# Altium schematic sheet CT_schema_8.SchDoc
size 274 x 160 mm
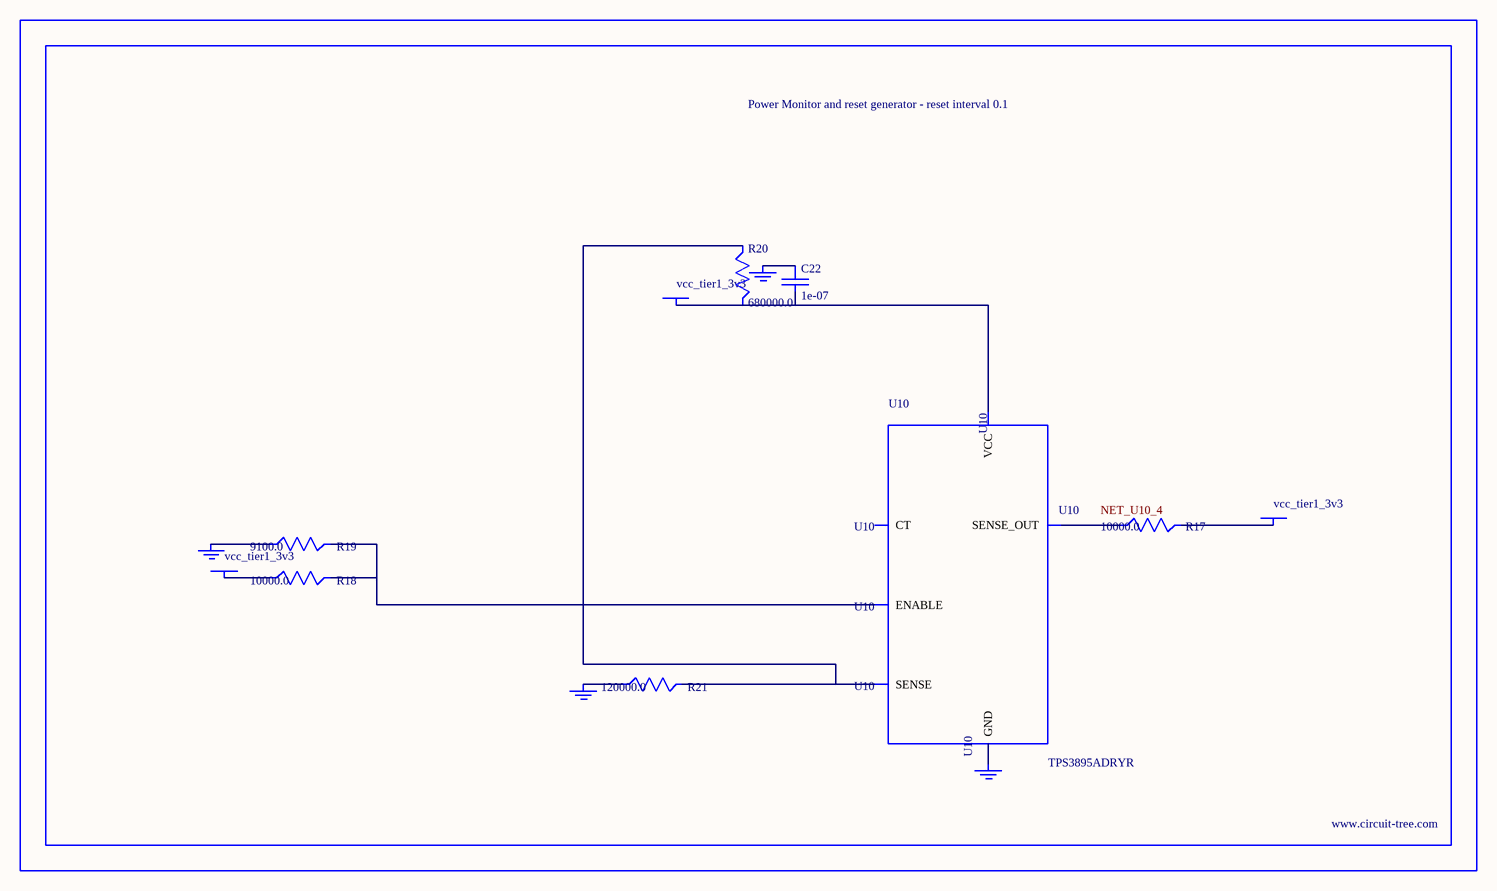
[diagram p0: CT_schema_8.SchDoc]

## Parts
BORDER7  (no value)
C22  1e-07  [C0402]
GND_INSTANCE_7_0  (no value)
GND_INSTANCE_7_1  (no value)
GND_INSTANCE_7_2  (no value)
GND_INSTANCE_7_3  (no value)
POWER_INSTANCE_7_0  vcc_tier1_3v3
POWER_INSTANCE_7_1  vcc_tier1_3v3
POWER_INSTANCE_7_2  vcc_tier1_3v3
R17  10000.0  [R0603]
R18  10000.0  [R0603]
R19  9100.0  [R0603]
R20  680000.0  [R0603]
R21  120000.0  [R0603]
U10  TPS3895ADRYR  [SON-6]

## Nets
NetC22_1: C22.1 GND_INSTANCE_7_2.0(GND)
NetC22_2: C22.2 POWER_INSTANCE_7_2.0(PWR) R20.2 U10.6(VCC)
NetGND_INSTANCE_7_0_0: GND_INSTANCE_7_0.0(GND) R19.1
NetGND_INSTANCE_7_1_0: GND_INSTANCE_7_1.0(GND) R21.1
NetGND_INSTANCE_7_3_0: GND_INSTANCE_7_3.0(GND) U10.2(GND)
NetPOWER_INSTANCE_7_0_0: POWER_INSTANCE_7_0.0(PWR) R18.1
NetPOWER_INSTANCE_7_1_0: POWER_INSTANCE_7_1.0(PWR) R17.2
NetR17_1: R17.1 U10.4(SENSE_OUT)
NetR18_2: R18.2 R19.2 U10.1(ENABLE)
NetR20_1: R20.1 R21.2 U10.3(SENSE)

Not connected (* = marked no-connect by the designer): U10 5(CT)

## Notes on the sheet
- Labels drawn without touching a wire or pin: NET_U10_4

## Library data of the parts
BORDER7 = BORDER_PAGE7
C22 = C0402C104K3RACTU
GND_INSTANCE_7_0-GND_INSTANCE_7_3 = GND
POWER_INSTANCE_7_0-POWER_INSTANCE_7_2 = PWR
R17 R18 = RC0603JR-0710KL
R19 = RC0603JR-079K1L
R20 = RC0603JR-07680KL
R21 = RC0603JR-07120KL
